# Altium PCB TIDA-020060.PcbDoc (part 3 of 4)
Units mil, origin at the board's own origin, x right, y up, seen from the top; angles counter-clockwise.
Board outline 2114.94 x 3612.21 mil, 4 copper layers (Top Layer, Signal Layer 1, Signal Layer 2, Bottom Layer), stack 61.811 mil thick; 272 components, 167 nets, 840 pads, 352 vias.
Unrouted connection lines stored in the file: 261.
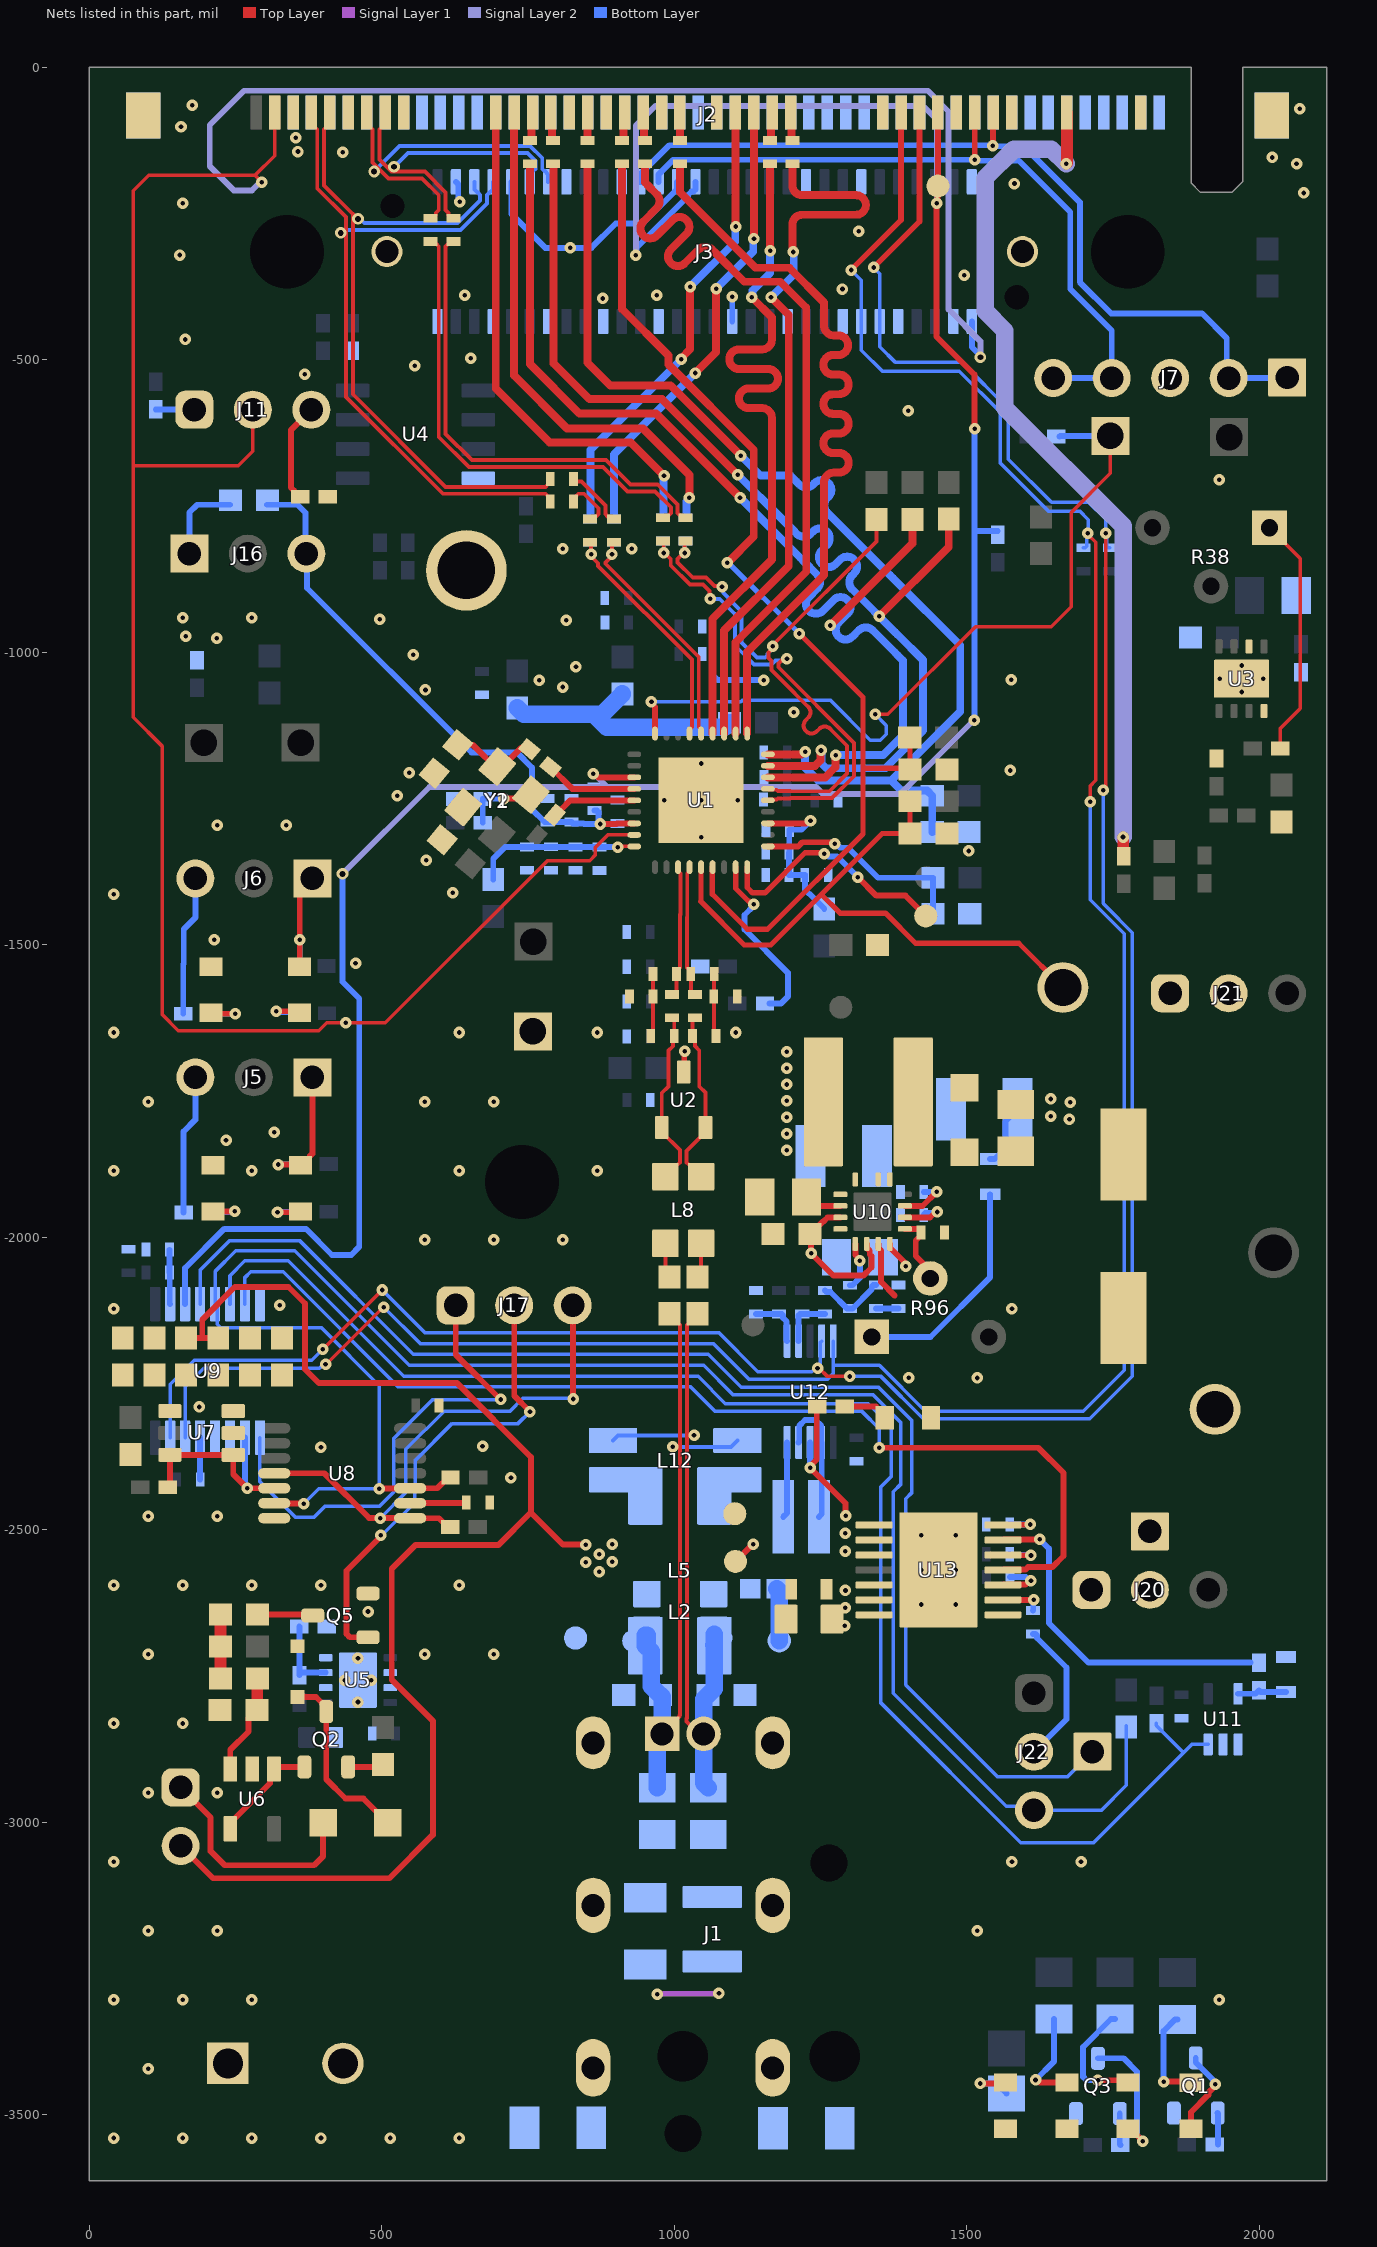
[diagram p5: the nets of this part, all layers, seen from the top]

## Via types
v1: diameter 19.68, hole 7.87, Top Layer to Bottom Layer, tented both sides, 333 vias
v2: diameter 19.68, hole 7.87, Top Layer to Bottom Layer, 10 vias
v3: diameter 20, hole 10, Top Layer to Bottom Layer, 7 vias
v4: diameter 50, hole 28, Top Layer to Bottom Layer, 2 vias

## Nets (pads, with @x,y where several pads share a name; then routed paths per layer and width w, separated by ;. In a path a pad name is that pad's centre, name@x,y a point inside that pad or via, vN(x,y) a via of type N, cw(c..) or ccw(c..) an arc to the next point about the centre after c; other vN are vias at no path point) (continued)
AE_MDIO: J8.1 R19.1 U1.36 | length 1352.1
  Top Layer w6: v1(1343.12,-1106.01) 1364.59,-1106.01 1514.69,-955.91 1644.26,-955.91 1678.02,-922.15 1678.02,-760.89 1745.25,-693.65 J8.1@1745.25,-629.91
  Top Layer w10: v1(960.75,-1084.6) 960.75,-1087.19 966.84,-1093.28 U1.36@966.84,-1138.68
  Bottom Layer w6: v1(960.75,-1084.6) 960.79,-1084.56 1113.73,-1084.56 1116.92,-1081.37 1266.21,-1081.37 1335.02,-1150.19 1351.61,-1150.19 1362.06,-1139.74 1362.06,-1124.95 v1(1343.12,-1106.01)
  Bottom Layer w10: R19.1@1658.4,-631.06 1659.55,-629.91 J8.1@1745.25,-629.91
AE_RESET_N: J2.26 J3.45 R20.1 TP13.1 U1.3 U9.3 | length 4542
  Top Layer w10: v1(861.53,-1207.49) 864.15,-1207.49 870.29,-1213.63 U1.3@931.41,-1213.63 ; v1@1447.74,-231.69 1449.56,-229.87 1449.56,-203.71 TP13.1@1450.43,-202.84 ; v1(1448.69,-232.32) 1447.74,-233.27 1447.74,-459.82 1513.1,-525.18 v1(1513.1,-617.84) ; TP13.1@1450.43,-200.02 J2.26@1450.43,-77
  Signal Layer 2 w10: v3(432.73,-1378.58) 581.23,-1230.08 885.38,-1230.08 ; v1(861.53,-1207.49) 862.8,-1207.49 885.38,-1230.08 ; v1(934.05,-321.37) 934.05,-99.29 967.38,-65.95 1425.39,-65.95 1448.69,-89.25 v1(1448.69,-232.32) ; v1(1512.24,-1115.65) 1385.6,-1242.29 1254.46,-1242.29 1242.25,-1230.08 885.38,-1230.08
  Bottom Layer w10: U9.3@163.56,-2113.84 163.56,-2052.49 230.7,-1985.35 370.12,-1985.35 414.72,-2029.94 447.48,-2029.94 461.36,-2016.06 461.36,-1591.68 432.73,-1563.06 v3(432.73,-1378.58) ; v1(934.05,-321.37) 935.74,-319.68 935.74,-307.93 1023.35,-220.32 1023.35,-218.18 1029.2,-212.32 1032.13,-212.32 1035.98,-208.46 J3.45@1035.98,-195.67 ; v1(1512.24,-1115.65) 1512.67,-1115.22 1512.67,-792.2 ; v1(1513.1,-617.84) 1512.67,-618.27 1512.67,-792.2 ; R20.1@1552.78,-792.63 1513.1,-792.63 1512.67,-792.2
AE_RX_CLK: R14.2 R54.2 R59.2 U1.27 | length 1893.6
  Top Layer w13.5: U1.27@1159.75,-1174.26 1217.32,-1174.26 1221.7,-1169.88 v1(1223.37,-1169.88)
  Top Layer w13.51: R54.2@851.26,-164.75 851.26,-504.76 890.34,-543.84 993.53,-543.84 v1(1113.25,-663.56)
  Bottom Layer w13.5: v1(1113.25,-663.56) 1147.6,-697.91 1198.63,-697.91 1208.77,-708.05 1213.54,-712.83 ccw(c1225.39,-700.98) 1237.23,-712.83 1239.64,-710.42 cw(c1251.48,-722.27) 1263.33,-710.42 cw(c1251.48,-722.27) 1263.33,-734.11 1260.92,-736.52 ccw(c1272.77,-748.36) 1260.92,-760.21 1368.6,-867.89 1373.38,-872.66 1488.62,-987.91 1488.62,-1101.13 1370.68,-1219.07 1248.07,-1219.07 1245.44,-1218.63 1223.36,-1196.55 v1(1223.37,-1169.88)
  Bottom Layer w13.51: 1370.68,-1219.07 1387.67,-1236.05 1431.69,-1236.05 R14.2@1440.75,-1245.11 R59.2@1440.75,-1306.71
AE_RX_CTRL: R31.1 R53.2 R67.2 U1.15 | length 1886.2
  Top Layer w9: U1.15@1065.26,-1367.03 1064.86,-1367.44 1064.86,-1413.46 1124.64,-1473.25 1159.14,-1473.25 1322.16,-1310.23 1322.16,-1198.02 ; v1(1213.28,-967.75) 1322.16,-1076.63 1322.16,-1198.02 ; R31.1@1402.3,-1145.38 1402.52,-1145.6 R67.2@1402.52,-1199.61 ; R67.2@1402.74,-1199.83 R67.2@1402.52,-1199.61 ; 1322.16,-1198.02 1400.93,-1198.02 R67.2@1402.52,-1199.61
  Top Layer w13.51: R53.2@910.69,-164.75 910.69,-413.48 989.87,-492.66 989.87,-507.77 1135.61,-653.51 1135.61,-802.02 v1(1090.59,-847.04)
  Bottom Layer w9: v1(1090.59,-847.04) 1092.56,-847.04 v1(1213.28,-967.75)
AE_RX_D0: R3.2 R55.2 U1.26 | length 1966.1
  Top Layer w13.5: U1.26@1159.75,-1193.94 1240.23,-1193.94 1249.47,-1184.71 1249.47,-1168.76 v1(1250.66,-1167.58)
  Top Layer w13.51: R55.2@792.85,-164.75 792.85,-164.9 793.45,-165.5 793.45,-505.87 854.74,-567.16 978.66,-567.16 1107.77,-696.27 v1(1108.05,-696.27) ; v1(1350.17,-938.39) 1468.87,-819.7 1468.87,-772.28 R3.2@1468.93,-772.21
  Bottom Layer w13.5: 1182.87,-771.09 1204.29,-792.51 1209.06,-797.28 ccw(c1220.91,-785.44) 1232.76,-797.28 1236.84,-793.2 cw(c1248.69,-805.04) 1260.53,-793.2 cw(c1248.69,-805.04) 1260.53,-816.89 1252.05,-825.37 ccw(c1263.9,-837.21) 1252.05,-849.06 ccw(c1263.9,-837.21) 1275.74,-849.06 1283.53,-841.27 cw(c1295.37,-853.12) 1307.22,-841.27 cw(c1295.37,-853.12) 1307.22,-864.96 1303.83,-868.36 ccw(c1315.67,-880.2) 1303.83,-892.05 1376.78,-965 1381.55,-969.77 1424.89,-1013.11 ; v1(1250.66,-1167.58) 1251.84,-1168.76 1251.84,-1190.11 1259.75,-1198.02 1360.54,-1198.02 1424.89,-1133.67
  Bottom Layer w13.51: v1(1108.05,-696.27) 1182.87,-771.09 ; 1424.89,-1133.67 1424.89,-1013.11
AE_RX_D1: R4.2 R56.2 U1.25 | length 2006.2
  Top Layer w13.5: U1.25@1159.75,-1213.63 1257.76,-1213.63 1275.03,-1196.36 1275.03,-1176.68 v1(1276.05,-1175.65)
  Top Layer w13.51: R56.2@753.36,-164.75 753.36,-165.23 753.1,-165.5 753.1,-507.09 837.54,-591.53 968.36,-591.53 v1(1112.2,-735.37) ; v1(1266.49,-953.97) 1406.92,-813.55 1406.92,-772.54 R4.2@1406.98,-772.48
  Bottom Layer w13.5: v1(1112.2,-735.37) 1215.72,-838.9 1220.5,-843.67 1244.19,-867.37 cw(c1232.34,-879.21) 1244.19,-891.06 1229.93,-905.32 ccw(c1241.77,-917.17) 1229.93,-929.01 ccw(c1241.77,-917.17) 1253.62,-929.01 1272.27,-910.35 cw(c1284.12,-922.2) 1295.97,-910.35 cw(c1284.12,-922.2) 1295.97,-934.04 1280.6,-949.41 ccw(c1292.45,-961.25) 1280.6,-973.1 ccw(c1292.45,-961.25) 1304.29,-973.1 1315.26,-962.13 cw(c1327.11,-973.97) 1338.95,-962.13 1376.75,-999.92 1381.52,-1004.7 1390.92,-1014.09 1390.92,-1141.47 1356.9,-1175.49 1276.21,-1175.49 v1(1276.05,-1175.65)
  Bottom Layer w13.51: v1(1266.49,-953.97) 1267.74,-952.73 1277.28,-952.73 1280.6,-949.41
AE_RX_N: R39.2 R58.2 U1.23 | length 808
  Top Layer w6.73: R39.2@980.32,-809.77 981.8,-811.25 v1(981.8,-829.98) 983.03,-829.98 993.73,-840.68 993.73,-851.12 1026.45,-883.84 1048.94,-883.84 1059.88,-894.78 1059.88,-906.48 v1(1061.39,-908) ; U1.23@1159.75,-1252.86 1161.31,-1251.3 1174.82,-1251.3 1176.65,-1249.48 1197.82,-1249.48 1198.27,-1249.02 1269.73,-1249.02 1307.04,-1211.71 1307.04,-1154.64 1177.72,-1025.32 1177.72,-1018.95 1183.2,-1013.48 1189.91,-1013.48 v1(1192.39,-1011)
  Bottom Layer w6.73: R58.2@980.32,-809.77 981.8,-811.25 v1(981.8,-829.98) ; v1(1061.39,-908) 1062.34,-908.95 1077.49,-908.95 1103.19,-934.65 1103.19,-987.78 1136.08,-1020.67 1165.75,-1020.67 1172.94,-1013.48 1189.91,-1013.48 v1(1192.39,-1011)
AE_RX_P: R5.2 R40.2 R57.2 U1.24 | length 1087.2
  Top Layer w6.73: R40.2@1019.02,-809.77 1017.38,-811.4 v1(1017.38,-829.98) 1016.16,-829.98 1005.46,-840.68 1005.46,-846.26 1031.31,-872.11 1053.8,-872.11 1068.17,-886.48 1079.88,-886.48 v1(1081.39,-888) ; U1.24@1159.75,-1233.17 1161.31,-1234.73 1174.54,-1234.73 1176.65,-1236.84 1197.82,-1236.84 1198.27,-1237.29 1264.87,-1237.29 1295.31,-1206.85 1295.31,-1159.5 1268.82,-1133.01 1266.44,-1130.63 ccw(c1256.98,-1140.08) 1247.53,-1130.63 1243.59,-1134.57 cw(c1234.14,-1125.12) 1224.69,-1134.57 cw(c1234.14,-1125.12) 1224.69,-1115.67 1228.63,-1111.72 ccw(c1219.18,-1102.27) 1228.63,-1092.82 1183.62,-1047.81 1165.99,-1030.18 1165.99,-1014.54 1160.98,-1009.53 1160.98,-1000.48 1168.38,-993.09 v1(1168.38,-989.58) 1168.38,-986.91 1345.18,-810.1 1345.18,-772.81 R5.2@1345.25,-772.75
  Bottom Layer w6.73: v1(1017.38,-829.98) 1017.38,-811.4 R57.2@1019.02,-809.77 ; 1083.87,-898.73 1114.92,-929.79 1114.92,-982.92 1140.94,-1008.94 1154.77,-1008.94 1158.72,-1005 1158.72,-1002.74 1168.38,-993.09 v1(1168.38,-989.58)
AE_STRP_1: R29.2 R35.2 TP4.1 U1.14 | length 1060.1
  Top Layer w9: U1.14@1045.58,-1367.03 1045.58,-1425.37 1045.17,-1425.78 1119.44,-1500.05 1164.64,-1500.05 1251.04,-1413.65 ; R29.2@1402.65,-1254.42 R35.2@1402.65,-1309.42 1355.28,-1309.42 1251.04,-1413.65 ; TP4.1@1664.13,-1572.77 1588.6,-1497.25 1412.41,-1497.25 1360.9,-1445.73 1283.13,-1445.73 1251.04,-1413.65
AE_STRP_DFT: TP5.1 U1.18 | length 416.9
  Top Layer w9: U1.18@1124.32,-1367.03 1124.32,-1401.57 1126.3,-1403.55 1133.77,-1411.02 1154.66,-1411.02 1223.19,-1342.49 1254.37,-1342.49 v1(1256.21,-1344.34)
  Top Layer w10: v1(1313.68,-1384.3) 1345.14,-1415.77 1394.94,-1415.77 TP5.1@1429.63,-1450.46
  Bottom Layer w10: v1(1256.21,-1344.34) 1258.83,-1344.34 1263.28,-1348.79 1278.17,-1348.79 v1(1313.68,-1384.3)
AE_TX_CLK: R51.2 U1.28 | length 1392.4
  Top Layer w13.51: R51.2@1009.46,-164.75 1009.46,-213.36 1138.63,-342.53 1196.4,-342.53 1255.62,-401.76 1255.62,-412.6 1255.62,-441.37 ccw(c1272.38,-441.37) 1272.38,-458.12 1280.21,-458.12 cw(c1280.21,-474.87) 1296.97,-474.87 cw(c1280.21,-474.87) 1280.21,-491.63 1271.32,-491.63 ccw(c1271.32,-508.38) 1254.56,-508.38 ccw(c1271.32,-508.38) 1271.32,-525.14 1281.25,-525.14 cw(c1281.25,-541.89) 1298,-541.89 cw(c1281.25,-541.89) 1281.25,-558.65 1271.32,-558.65 ccw(c1271.32,-575.4) 1254.56,-575.4 ccw(c1271.32,-575.4) 1271.32,-592.16 1281.25,-592.16 cw(c1281.25,-608.91) 1298,-608.91 cw(c1281.25,-608.91) 1281.25,-625.67 1271.32,-625.67 ccw(c1271.32,-642.42) 1254.56,-642.42 ccw(c1271.32,-642.42) 1271.32,-659.18 1281.25,-659.18 cw(c1281.25,-675.93) 1298,-675.93 cw(c1281.25,-675.93) 1281.25,-692.69 1272.38,-692.69 ccw(c1272.38,-709.44) 1255.62,-709.44 1255.62,-749.71 1255.62,-867.9 1124.32,-999.21 U1.28@1124.32,-1138.68
AE_TX_CTRL: R52.2 U1.29 | length 1391.4
  Top Layer w13.51: R52.2@950.04,-164.75 950.04,-197.01 954.82,-201.78 969.83,-216.8 cw(c957.98,-228.64) 969.83,-240.49 946.65,-263.67 ccw(c958.5,-275.51) 946.65,-287.36 ccw(c958.5,-275.51) 970.35,-287.36 997.01,-260.7 cw(c1008.85,-272.55) 1020.7,-260.7 cw(c1008.85,-272.55) 1020.7,-284.4 994.04,-311.06 ccw(c1005.89,-322.9) 994.04,-334.75 ccw(c1005.89,-322.9) 1017.74,-334.75 1040.91,-311.57 cw(c1052.76,-323.42) 1064.61,-311.57 1069.38,-316.35 1119.45,-366.42 1180.99,-366.42 1225.3,-410.73 1225.3,-861.89 1104.63,-982.56 U1.29@1104.63,-1138.68
AE_TX_D2: R48.2 U1.31 | length 1264.8
  Top Layer w13.51: U1.31@1065.26,-1138.68 1065.26,-942.61 1166.64,-841.23 1166.64,-606 1166.64,-599.24 ccw(c1149.89,-599.24) 1149.89,-582.49 1126.98,-582.49 cw(c1126.98,-565.73) 1110.23,-565.73 cw(c1126.98,-565.73) 1126.98,-548.98 1160.21,-548.98 ccw(c1160.21,-532.23) 1176.97,-532.23 ccw(c1160.21,-532.23) 1160.21,-515.47 1110.58,-515.47 cw(c1110.58,-498.72) 1093.82,-498.72 cw(c1110.58,-498.72) 1110.58,-481.96 1149.89,-481.96 ccw(c1149.89,-465.21) 1166.64,-465.21 1166.64,-434.25 1166.64,-427.32 v1(1132.4,-393.08) ; R48.2@1163.04,-164.75 1163.31,-165.02 1163.31,-312.81 v1(1163.58,-313.08)
  Bottom Layer w13.51: v1(1132.4,-393.08) 1133.58,-391.89 1133.58,-381.65 1163.58,-351.65 v1(1163.58,-313.08)
AE_TX_D3: R47.2 U1.30 | length 1271.7
  Top Layer w13.51: U1.30@1084.95,-1138.68 1084.95,-962.67 1195.48,-852.15 1195.48,-423.41 v1(1165.14,-393.08) ; R47.2@1201.66,-164.75 1201.66,-165.54 1201.66,-201.67 ccw(c1218.41,-201.67) 1218.41,-218.42 1310.45,-218.42 cw(c1310.45,-235.18) 1327.21,-235.18 cw(c1310.45,-235.18) 1310.45,-251.93 1218.41,-251.93 ccw(c1218.41,-268.69) 1201.66,-268.69 1201.66,-308.95 1201.66,-314.31 v1(1202.83,-315.48)
  Bottom Layer w13.51: v1(1165.14,-393.08) 1204.01,-354.21 1204.01,-316.66 v1(1202.83,-315.48)
AE_TX_N: R46.2 R50.2 U1.33 | length 422
  Top Layer w6.73: R46.2@855.56,-811.74 857.65,-813.83 v1(857.65,-832.13) 857.65,-835.63 869.65,-847.63 869.65,-852.26 1029.87,-1012.48 1029.87,-1127.82 1025.89,-1131.8 U1.33@1025.89,-1138.68
  Bottom Layer w6.73: R50.2@855.56,-811.74 857.65,-813.83 v1(857.65,-832.13)
AE_TX_P: R45.2 R49.2 U1.32 | length 422
  Top Layer w6.73: R45.2@896.44,-811.74 893.23,-814.95 v1(893.23,-832.13) 893.23,-835.63 882.46,-846.4 882.46,-848.48 1041.6,-1007.62 1041.6,-1127.82 1045.58,-1131.8 U1.32@1045.58,-1138.68
  Bottom Layer w6.73: v1(893.23,-832.13) 893.23,-814.95 R49.2@896.44,-811.74
AE_VSLEEP: C2.1 C3.1 C37.1 C43.2 J16.3 R2.1 U1.7 | length 1029.5
  Top Layer w10: v1(873.27,-1293.31) 900.67,-1293.31 901.75,-1292.23 U1.7@931.41,-1292.23
  Bottom Layer w10: R2.1@303.38,-747.51 355.69,-747.51 369.44,-761.26 369.44,-829.71 371.91,-832.18 371.91,-889.72 653.05,-1170.86 730.4,-1170.86 756.35,-1196.81 756.35,-1268 778.23,-1289.88 C2.1@782.73,-1289.88 C3.1@824.02,-1289.88 826.52,-1292.38 844.81,-1292.38 845.74,-1293.31 v1(873.27,-1293.31) ; C37.1@863.34,-1270.2 867.84,-1270.2 870.34,-1272.7 870.34,-1287.76 873.27,-1290.69 v1(873.27,-1293.31) ; C43.2@902.46,-1292.31 901.96,-1292.81 873.77,-1292.81 v1(873.27,-1293.31)
AE_WAKE: J2.98 J3.30 J11.2 U1.8 | length 5029.2
  Top Layer w6: J11.2@279.34,-585.09 279.34,-655.89 254.29,-680.94 76.45,-680.94 75.02,-679.52 ; v1(294.51,-196.06) 283.02,-184.57 ; J2.98@316.57,-77 316.77,-77.2 316.77,-150.82 283.02,-184.57 ; U1.8@931.41,-1312.06 886.33,-1312.06 865.05,-1333.33 865.05,-1345.98 855.09,-1355.93 783.01,-1355.93 505.98,-1632.96 v1(438.08,-1632.96) 405.79,-1632.96 392.35,-1646.4 151.88,-1646.4 124.14,-1618.66 124.14,-1160.06 75.02,-1110.95 75.02,-679.52 ; 75.02,-679.52 75.02,-210.94 101.4,-184.57 283.02,-184.57
  Signal Layer 2 w10: v1(294.51,-196.06) 291.89,-196.06 277.82,-210.13 246.82,-210.13 205.84,-169.15 205.84,-98.47 264.31,-40 1433.37,-40 1468.69,-75.32 1468.69,-288.08 1468.56,-288.21 1468.56,-413.64 1522.97,-468.05 v3(1522.97,-495.34)
  Bottom Layer w10: J3.30@1508.43,-434.25 1508.43,-478.09 1522.97,-492.63 v3(1522.97,-495.34)
AE_XI: R69.1 U1.5 | length 143
  Top Layer w10: R69.1@794.84,-1268.33 806.35,-1268.33 821.82,-1252.86 U1.5@931.41,-1252.86
AE_XO: R30.1 U1.4 | length 158.5
  Top Layer w10: R30.1@788.27,-1196.02 825.43,-1233.17 U1.4@931.41,-1233.17
BAW_NC: C28.1 R30.2 Y1.1 Y2.1 | length 154.2
  Top Layer w10: C28.1@629.9,-1158.23 630.18,-1157.96 655.3,-1157.96 Y2.1@699.22,-1201.88 ; Y2.1@701.63,-1199.47 735.45,-1165.65 735.51,-1165.65 738.04,-1163.12 749.55,-1163.12 R30.2@752.08,-1165.65
BOOST_PG: U10.4
comp_out: R86.1 U7.1 U7.6 U8.5 U9.10 | length 366.5
  Top Layer w10: R86.1@134.18,-2427.1 137.62,-2423.65 U7.6@137.62,-2371.68 U7.1@245.89,-2371.68 245.89,-2404.99 v1(269.64,-2428.74) U8.5@316.01,-2428.74
  Bottom Layer w10: U9.10@265.93,-2342.19 265.93,-2422.32 269.64,-2426.03 v1(269.64,-2428.74)
DUT_VDD1P0: J2.12 R16.1 | length 1515.3
  Top Layer w19.68: v1(1766.86,-1315.6) 1767.4,-1316.14 1767.4,-1347.92 R16.1@1767.94,-1348.46
  Top Layer w20: v1(1669.68,-164.74) 1670.9,-163.51 J2.12@1670.9,-77
  Signal Layer 2 w10: v1(1766.86,-1315.6) v1@1766.86,-1315.12
  Signal Layer 2 w30: v1(1669.68,-164.74) 1644.5,-139.56 1580.45,-139.56 1531.13,-188.88 1531.13,-416.38 1565.03,-450.28 1565.03,-582.06 1766.86,-783.9 v1@1766.86,-1315.12
EN: J22.2 R112.1 | length 250.5
  Bottom Layer w10: R112.1@1612.91,-2677.88 1617.41,-2677.88 1619.91,-2680.38 1619.91,-2684.88 1670.06,-2735.04 1670.06,-2823.53 J22.2@1614.54,-2879.06
EN_detection: J17.2 Q5.1 | length 809
  Top Layer w10: Q5.1@476.26,-2683.53 445.22,-2683.53 439.36,-2677.68 439.36,-2569.76 498.34,-2510.78 v1(498.34,-2509.39) ; J17.2@726.13,-2116.18 726.13,-2270.7 v1(753.11,-2297.68)
  Bottom Layer w6: v1(498.34,-2509.39) 499.97,-2509.39 555.92,-2453.43 555.92,-2436.37 557.32,-2434.97 557.32,-2380.7 619.9,-2318.12 732.67,-2318.12 v1(753.11,-2297.68)
EN_detection_SoC: J17.1 U9.9 | length 841.5
  Top Layer w10: J17.1@626.13,-2116.18 626.13,-2200.33 702.82,-2277.02 v1(702.93,-2277.02)
  Bottom Layer w6: U9.9@291.52,-2342.19 291.52,-2417.88 351.58,-2477.95 384.59,-2477.95 402.62,-2459.92 495.76,-2459.92 520.65,-2435.03 520.65,-2343.51 587.03,-2277.13 702.82,-2277.13 v1(702.93,-2277.02)
EN_P17: R62.2 U1.17 | length 309.5
  Top Layer w9: U1.17@1104.63,-1367.03 1104.63,-1403.1 1127.06,-1425.52 1128.02,-1425.52 1132.95,-1430.45 v1(1135.57,-1430.45)
  Bottom Layer w10: v1(1135.57,-1430.45) 1135.57,-1433.07 1119.79,-1448.85 1119.79,-1473.35 1193.92,-1547.48 1193.92,-1588.43 1182.43,-1599.92 R62.2@1162.74,-1599.92
ext_pwr_supply: J14.2 J20.1 J21.1
FB: R96.2 R101.2 U10.9 | length 124.7
  Top Layer w10: U10.9@1393.93,-1985.5 1394.2,-1985.78 1419.12,-1985.78 1421.62,-1988.28 1421.62,-1996.11 1412.48,-2005.24 1412.48,-2031.82 1437.4,-2056.74 R96.2@1437.4,-2070.01
GND: C2.2 C3.2 C4.2 C5.1 C6.2 C7.1 C8.2 C11.2 C12.2 C13.2 C14.1 C15.2 C16.2 C17.2 C18.1 C19.1 C22.2 C23.2 C24.2 C25.2 C26.1 C27.2 C28.2 C29.2 C30.1 C31.1 C32.1 C35.2 C37.2 C38.2 C39.2 C40.1 C41.2 C42.2 C43.1 C44.2 C45.2 C46.1 C47.2 C48.1 C49.2 C50.2 C51.2 C52.2 C53.2 C54.1 C55.1 C56.2 C57.2 C58.2 C59.2 C60.2 C61.2 C62.2 C63.2 C64.1 C65.2 C67.2 C68.2 C69.2 C70.2 D1.1 D2.2 D3.2 D4.2 D7.1 D8.1 D13.1 D15.1 J2.4 J2.9 J2.11 J2.13 J2.15 J2.17 J2.18 J2.19 J2.21 J2.23 J2.24 J2.25 J2.27 J2.29 J2.31 J2.32 J2.33 J2.35 J2.37 J2.39 J2.41 J2.43 J2.45 J2.47 J2.49 J2.50 J2.51 J2.53 J2.55 J2.56 J2.57 J2.59 J2.61 J2.62 J2.63 J2.65 J2.66 J2.67 J2.69 J2.71 J2.73 J2.75 J2.77 J2.79 J2.81 J2.83 J2.84 J2.85 J2.87 J2.89 J2.90 J2.91 J2.93 J2.95 J2.96 J2.MP1 J2.MP2 J2.MP3 J2.MP4 J3.1 J3.4 J3.7 J3.10 J3.13 J3.17 J3.20 J3.23 J3.26 J3.29 J3.32 J3.35 J3.38 J3.41 J3.44 J3.51 J3.54 J3.60 J3.MH1 J3.MH2 J7.3 J13.1 J14.1 Q1.2 Q3.2 Q5.2 R13.1 R18.2 R24.1 R35.1 R37.1 R41.2 R59.1 R60.2 R67.1 R80.1 R87.1 R88.1 R89.1 R92.1 R99.1 R101.1 R102.1 R106.2 R107.2 R108.1 R111.1 R115.1 R116.1 TP8.1 TP24.1 U1.37 U2.3 U3.4 U3.9 U4.4 U5.2 U5.4 U5.6 U5.7 U5.9 U6.2 U7.2 U8.7 U9.8 U10.1 U10.7 U10.16 U11.1 U11.2 U12.7 U12.9 U13.1 U13.15 Y1.2 Y2.2 | length 1179.2
  Top Layer w10: U2.3@1015.91,-1717.4 1016.86,-1716.44 1016.86,-1682.58 v1(1017.92,-1681.52) ; U10.7@1348.65,-2011.09 1348.65,-2017.63 1353.34,-2022.31 1353.34,-2076.11 1376.68,-2099.45
  Signal Layer 1 w10: v1(970.68,-3293.89) 971.66,-3292.9 1075.18,-3292.9 v1(1076.16,-3291.92)
  Bottom Layer w10: J3.32@626.54,-195.67 630.39,-199.53 630.39,-224.3 633.31,-227.22 v1(633.31,-229.84) ; J3.35@721.02,-195.67 721.02,-250.29 779.2,-308.47 v1(822.19,-308.47) 858.03,-308.47 899.72,-266.78 946.18,-266.78 1004.49,-208.46 J3.44@1004.49,-195.67 ; 1066.99,-1040 1074.38,-1047.4 v1(1152.44,-1047.4) ; v1(1098.86,-392.29) 1098.86,-434.37 J3.17@1098.98,-434.25 ; U12.9@1212.4,-2350.47 1213.3,-2349.56 1213.3,-2321.8 1223.18,-2311.92 1240.99,-2311.92 1250.86,-2321.8 1250.86,-2349.56 U12.7@1251.77,-2350.47 1251.77,-2472.88 R108.1@1247.07,-2477.58 ; R106.2@1257.4,-2090.82 1259.9,-2093.32 1266.95,-2093.32 1295.33,-2121.7 R102.1@1299.83,-2121.7 1304.33,-2121.7 1337.38,-2088.65 1337.38,-2083.94 1339.88,-2081.44 C62.2@1344.38,-2081.44
  other v1: 41.54,-3539.46 159.65,-3539.46 277.76,-3539.46 395.87,-3539.46 513.98,-3539.46 632.09,-3539.46 100.59,-3421.35 41.54,-3303.24 159.65,-3303.24 277.76,-3303.24 1931.3,-3303.24 100.59,-3185.13 218.7,-3185.13 1517.92,-3185.13 41.54,-3067.02 1576.97,-3067.02 1695.08,-3067.02 100.59,-2948.91 218.7,-2948.91 41.54,-2830.8 159.65,-2830.8 459.09,-2794.15 436.45,-2756.75 481.72,-2756.75 459.09,-2719.35 100.59,-2712.69 573.03,-2712.69 691.14,-2712.69 476.31,-2639.49 1421.82,-2627.45 1480.87,-2627.45 41.54,-2594.58 159.65,-2594.58 277.76,-2594.58 395.87,-2594.58 632.09,-2594.58 1421.82,-2568.4 1480.87,-2568.4 1421.82,-2509.34 1480.87,-2509.34 100.59,-2476.47 218.7,-2476.47 720.58,-2410.98 395.87,-2358.35 672,-2356.89 187.89,-2289.77 1517.92,-2240.24 1400.25,-2239.8 41.54,-2122.13 1576.97,-2122.13 325.42,-2115.63 573.03,-2004.02 691.14,-2004.02 809.25,-2004.02 41.54,-1885.91 277.76,-1885.91 632.09,-1885.91 868.31,-1885.91 233.53,-1834.16 316.16,-1820.39 100.59,-1767.8 573.03,-1767.8 691.14,-1767.8 41.54,-1649.69 632.09,-1649.69 868.31,-1649.69 1104.53,-1649.69 454.92,-1531.58 213.17,-1491.33 41.54,-1413.47 621.17,-1410.84 575.67,-1355.2 1502.8,-1339.4 218.7,-1295.36 336.81,-1295.36 526.01,-1245.23 547.07,-1205.45 1574.33,-1201.77 1203.72,-1101.99 1969.45,-1067.58 574.47,-1064.22 809.25,-1059.14 768.7,-1047.62 1576.06,-1047.06 1932.05,-1044.94 2006.85,-1044.94 831.71,-1024.71 1969.45,-1022.31 553.74,-1004.04 217.99,-976.11 164.83,-972.55 814.89,-944.96 496.47,-943.08 159.65,-941.03 277.76,-941.03 809.25,-822.92 927.36,-822.92 1931.3,-704.81 1399.8,-586.7 368.03,-524.24 555.82,-510.3 651.77,-496.96 163.69,-465.08 877.35,-394.98 641.45,-389.79 969.71,-389.81 1287.28,-378.82 1495.43,-355.21 154.58,-320.73 1315.01,-280.23 159.65,-232.37 2075.5,-214.67 1581.29,-198.48 2063.43,-164.48 2022.13,-153.99 432.77,-144.78 356.49,-143.78 352.98,-120.53 156.58,-101.18 2068.83,-70.45 175.61,-64.56
  other v2: 1045.58,-1315.85 982.59,-1252.86 1045.58,-1252.86 1108.57,-1252.86 1045.58,-1189.87
GND_WIRE: C19.2 J1.S1 J1.S2 J1.S3 J1.S4 J1.S5 J1.S6 R18.1
GPIO6: U9.11
GPIO7: U9.12
GPIO_3: R6.2 R24.2 U1.19 | length 372.4
  Top Layer w10: U1.19@1159.75,-1331.6 1211.3,-1331.6 1211.44,-1331.74 1218.68,-1324.49 1268.75,-1324.49 1271.59,-1327.34 v1(1274.21,-1327.34)
  Bottom Layer w10: v1(1274.21,-1327.34) 1276.83,-1327.34 1283.28,-1333.79 1296.67,-1333.79 1348.02,-1385.13 R6.2@1442.26,-1385.13 1441.85,-1385.55 R24.2@1441.85,-1446.62
GPIO_4: J2.7
GPIO_5: J2.5
GPIO_6: J2.3
GPIO_7: J2.1
High_side_sw_VIN: C67.1 C68.1 J20.2 U13.12 U13.13 U13.14
  other v1: 1291.47,-2664.04 1292.05,-2633.33 1292.36,-2603.5
HSS_EN: J23.1 U9.4 | length 2281.2
  Bottom Layer w6: U9.4@189.15,-2113.84 189.15,-2056.26 240.09,-2005.32 359.16,-2005.32 553.28,-2199.45 1057.73,-2199.45 1114.25,-2255.97 1348.84,-2255.97 1406.03,-2313.15 1406.03,-2436.01 1395.16,-2446.88 1395.16,-2765.01 1551.69,-2921.54 1672.06,-2921.54 J23.1@1714.54,-2879.06
HSS_FAULT: U9.7 U13.4 | length 1865.2
  Top Layer w10: v1(1350.28,-2359.49) 1622.08,-2359.49 1665.05,-2402.46 1665.05,-2544.51 1645.95,-2563.61 1604.3,-2563.61 1600.41,-2567.49 1562.49,-2567.49 U13.4@1561.58,-2568.4
  Bottom Layer w6: U9.7@265.93,-2113.84 265.93,-2068.49 275.53,-2058.89 331.53,-2058.89 528.22,-2255.58 1027.75,-2255.58 1069.62,-2297.45 1320.71,-2297.45 1350.28,-2327.02 v1(1350.28,-2359.49)
HSS_SNS: R70.1 U9.6 U11.3 | length 2583.5
  Bottom Layer w6: U9.6@240.34,-2113.84 240.34,-2065.24 265.61,-2039.97 339.97,-2039.97 537.49,-2237.49 1040.56,-2237.49 1087.12,-2284.05 1331.08,-2284.05 1370.28,-2323.24 1370.28,-2409.23 1353.12,-2426.39 1353.12,-2795.91 1591.78,-3034.57 1716.45,-3034.57 1870.55,-2880.47 ; R70.1@1823.87,-2830.32 1823.87,-2834.26 1870.08,-2880.47 1870.55,-2880.47 ; U11.3@1912.34,-2866.68 1884.35,-2866.68 1870.55,-2880.47
MDC: J2.20 J3.42 J7.1 J7.2 | length 1480
  Top Layer w10: v1(1543.97,-133.83) 1544.45,-133.36 1544.45,-77.47 J2.20@1544.92,-77
  Bottom Layer w10: J3.42@941.5,-195.67 941.5,-182.87 991.39,-132.98 1543.12,-132.98 1544.82,-134.69 1597.1,-134.69 1693.01,-230.6 1693.01,-367.05 1746.64,-420.68 1902.12,-420.68 1944.19,-462.75 1944.19,-527.73 J7.2@1947.5,-531.05 2046.5,-531.05 J7.1@2047.5,-530.05
MDIO: J2.22 J3.43 J7.4 J7.5 | length 1257.9
  Top Layer w10: v1(1513.42,-157.83) J2.22@1513.42,-77
  Bottom Layer w10: J3.43@972.99,-195.67 972.99,-182.87 998.04,-157.83 v1(1513.42,-157.83) 1515.28,-159.68 1589.11,-159.68 1676.57,-247.15 1676.57,-378.92 1747.5,-449.85 J7.4@1747.5,-531.05 J7.5@1647.5,-531.05
NetC7_2: C7.2 C9.1 R7.2 | length 107.6
  Top Layer w6.73: R7.2@959.71,-1655.41 959.71,-1650.91 963.44,-1647.18 C7.2@963.44,-1588.23 ; C7.2@963.44,-1588.23 C9.1@963.48,-1549.41
NetC21_2: C21.2 C27.1 R10.1 | length 107.8
  Top Layer w6.73: C21.2@1068.06,-1549.41 1067.7,-1549.77 1067.7,-1588.01 C27.1@1067.35,-1588.37 1067.35,-1647.35 1070.9,-1650.91 R10.1@1070.9,-1655.41
NetC50_1: C50.1 R79.2 U6.3 | length 173.8
  Top Layer w10: U6.3@240.87,-2908.58 240.87,-2875.74 271.81,-2844.81 271.81,-2821.66 285.51,-2807.96 C50.1@286.49,-2807.96
  Top Layer w20: C50.1@287,-2807.45 R79.2@287,-2753.78
NetC52_1: C52.1 R82.1 R88.2 U7.4
NetC53_1: C53.1 R83.1 R89.2 U7.3
NetC59_1: C59.1 U10.2 | length 64
  Top Layer w10: C59.1@1225.97,-1930.98 1241.12,-1946.13 U10.2@1283.69,-1946.13
NetC60_1: C60.1 U10.10 | length 84.7
  Top Layer w10: U10.10@1393.93,-1965.82 1437.04,-1965.82 1446.35,-1956.5 v1(1449.06,-1956.5)
  Bottom Layer w10: C60.1@1426.24,-1961.95 1426.24,-1960.91 1428.74,-1958.41 1447.15,-1958.41 v1(1449.06,-1956.5)
NetC61_1: C61.1 R103.2 U10.8 | length 49.4
  Top Layer w10: U10.8@1368.34,-2011.09 1368.34,-2017.63 1393.35,-2042.63 1393.35,-2047.5 v1(1395.2,-2049.35)
NetC62_1: C62.1 R103.1 | length 38.9
  Bottom Layer w10: C62.1@1344.38,-2121.44 R103.1@1383.31,-2121.44
NetD1_2: D1.2 R61.1 | length 96.1
  Top Layer w10: v1(1522.73,-3446.21) 1564.52,-3446.21 D1.2@1566.18,-3444.55
  Bottom Layer w10: v1(1522.73,-3446.21) 1550.61,-3446.21 R61.1@1567.65,-3463.24
NetD4_1: D4.1 D11.2 Q2.3 | length 315.1
  Top Layer w10: D4.1@355.77,-2785.55 387.26,-2785.55 404.9,-2803.19 Q2.3@404.9,-2810.57 404.9,-2926.15 437.87,-2959.13 468.29,-2959.13 D11.2@509.79,-3000.63
NetD5_1: D5.1 J5.1 R25.1 | length 240.3
  Top Layer w10: v1(322.53,-1875.41) 359.58,-1875.41 D5.1@361.12,-1876.96 365.06,-1876.96 375.81,-1866.21 375.81,-1862.28 381.12,-1856.96 J5.1@381.12,-1726.33
  Bottom Layer w10: v1(322.53,-1875.41) 323.03,-1874.91 361.45,-1874.91 R25.1@361.96,-1874.4
NetD5_2: D5.2 R27.1 | length 80.5
  Top Layer w10: v1(321.53,-1956.88) 359.94,-1956.88 D5.2@361.12,-1955.7
  Bottom Layer w10: v1(321.53,-1956.88) 321.85,-1956.56 361.37,-1956.56 R27.1@361.69,-1956.24
NetD6_1: D6.1 J6.1 R26.1 | length 206.2
  Top Layer w10: D6.1@358.9,-1537.5 359.69,-1536.71 v1(359.69,-1490.91) 359.69,-1407.77 J6.1@381.12,-1386.33
  Bottom Layer w10: R26.1@358.08,-1536.11 359.69,-1534.5 v1(359.69,-1490.91)
NetD6_2: D6.2 R28.1 | length 82.2
  Top Layer w10: v1(319.15,-1613.33) 355.99,-1613.33 D6.2@358.9,-1616.24
  Bottom Layer w10: v1(319.15,-1613.33) 320.91,-1615.1 357.19,-1615.1 R28.1@358.95,-1616.86
NetD7_2: D7.2 R43.2 | length 78.8
  Top Layer w10: D7.2@211.12,-1955.7 211.42,-1955.4 v1(248.63,-1955.4)
  Bottom Layer w10: R43.2@208.34,-1957.57 209.43,-1956.49 247.55,-1956.49 v1(248.63,-1955.4)
NetD8_2: D8.2 R44.2 | length 82.9
  Top Layer w10: D8.2@208.12,-1615.7 210.18,-1617.77 v1(249.2,-1617.77)
  Bottom Layer w10: R44.2@207.65,-1617.64 v1@248.65,-1617.64
NetD9_1: D9.1 Q3.3 | length 233.8
  Top Layer w10: D9.1@1775.47,-3523.29 1779.41,-3523.29 1800.72,-3544.6 v1(1800.72,-3544.95)
  Bottom Layer w10: Q3.3@1723.95,-3403.16 1767.93,-3403.16 1790.86,-3426.09 1790.86,-3534.25 1800.72,-3544.12 v1(1800.72,-3544.95)
NetD9_2: D9.2 R33.1 | length 206
  Top Layer w10: v1(1724.02,-3440.78) 1771.71,-3440.78 D9.2@1775.47,-3444.55
  Bottom Layer w10: v1(1724.02,-3440.78) 1704.48,-3440.78 1698.62,-3434.93 1698.62,-3383.84 1746.4,-3336.05 R33.1@1752.9,-3336.05
NetD10_1: D10.1 Q1.3 | length 152.6
  Top Layer w10: D10.1@1883.02,-3523.86 1883.02,-3495.38 1912.71,-3465.7 1912.71,-3462.02 1924.73,-3449.99 v1(1924.73,-3447.37)
  Bottom Layer w10: Q1.3@1891.2,-3402.41 1891.2,-3410.29 1922.88,-3441.96 1922.88,-3445.52 v1(1924.73,-3447.37)
NetD10_2: D10.2 R1.1 | length 166.2
  Top Layer w10: v1(1836.21,-3443.01) 1880.91,-3443.01 D10.2@1883.02,-3445.12
  Bottom Layer w10: v1(1836.21,-3443.01) 1836.21,-3356.63 1856.21,-3336.63 R1.1@1860.09,-3336.63
NetD11_1: D11.1 J15.1 | length 412.3
  Top Layer w10: J15.1@156,-2940.11 207.28,-2991.39 207.28,-3049.17 231.39,-3073.28 384.11,-3073.28 399.55,-3057.85 D11.1@399.55,-3000.63 D11.1@388.16,-3012.02
NetD12_2: D12.2 L9.2 U10.13 U10.14
NetD13_2: D13.2 R109.1 | length 78.5
  Top Layer w10: R109.1@1291.4,-2288.94 1344.54,-2288.94 1359.69,-2304.09 D13.2@1359.69,-2308.03
NetD15_2: D15.2 R66.1 | length 172.5
  Top Layer w10: v1(1617.26,-3440.16) 1619.96,-3440.16 1624.35,-3444.55 D15.2@1670.83,-3444.55
  Bottom Layer w10: v1(1617.26,-3440.16) 1648.55,-3408.88 R66.1@1648.55,-3336.05
NetFB1_1: FB1.1 L7.2 | length 90.7
  Bottom Layer w30: FB1.1@1174.93,-2600.53 1179.13,-2604.74 L7.2@1179.13,-2689.46
NetJ5_3: J5.3 R43.1 | length 239.5
  Bottom Layer w10: R43.1@161.1,-1957.57 161.1,-1818.95 181.12,-1798.93 J5.3@181.12,-1726.33
NetJ6_3: J6.3 R44.1 | length 239.9
  Bottom Layer w10: R44.1@160.4,-1617.64 160.4,-1533.02 161.24,-1532.18 161.24,-1473.22 181.12,-1453.35 J6.3@181.12,-1386.33
NetJ11_1: J11.1 R21.1 | length 66
  Bottom Layer w10: R21.1@113.52,-584.66 178.92,-584.66 J11.1@179.34,-585.09
NetJ11_3: J11.3 R41.1 | length 172.2
  Top Layer w10: R41.1@360.21,-733.96 356.27,-733.96 349.46,-727.15 349.46,-723.21 344.37,-718.12 344.37,-620.07 J11.3@379.34,-585.09
NetJ16_1: J16.1 R2.2 | length 145.3
  Bottom Layer w10: J16.1@170.82,-831.09 170.82,-761 184.31,-747.51 R2.2@240.39,-747.51
NetL3_2: L3.2 R71.1 R73.1 | length 443.8
  Bottom Layer w30: L3.2@731.41,-1094.76 742.59,-1105.94 862.4,-1105.94 ; R73.1@911.06,-1070.71 911.06,-1071.69 876.81,-1105.94 862.4,-1105.94 ; R71.1@1094.2,-1120.21 1086.19,-1128.22 928.72,-1128.22 884.67,-1128.22 862.4,-1105.94
NetQ1_1: Q1.1 R68.2 | length 53.7
  Bottom Layer w10: Q1.1@1928.6,-3496.9 1928.93,-3497.23 1928.93,-3549.97 R68.2@1929.26,-3550.3
NetQ2_1: Q2.1 U6.1 U6.4 | length 186.6
  Top Layer w10: U6.4@240.87,-3010.95 240.87,-3001.1 308.86,-2933.11 308.86,-2915.4 U6.1@315.67,-2908.58 319.2,-2905.06 Q2.1@367.49,-2905.06
NetQ2_2: Q2.2 R77.1 | length 61.7
  Top Layer w10: Q2.2@442.3,-2905.06 497.84,-2905.06 R77.1@502.17,-2900.74
NetQ3_1: Q3.1 R93.2 | length 54.4
  Bottom Layer w10: Q3.1@1761.35,-3497.65 1761.35,-3550.6 R93.2@1762.35,-3551.6
NetQ5_3: Q5.3 R81.1 | length 97
  Top Layer w10: R81.1@287.19,-2644.83 366.1,-2644.83 372.96,-2651.7 Q5.3@381.33,-2651.7
NetR34_2: R34.2 R38.1 | length 413.9
  Top Layer w6: R38.1@2017.2,-786.9 2069.8,-839.49 2069.8,-1095.84 2035.18,-1130.47 2035.18,-1164.08 R34.2@2035.61,-1164.5
NetR76_1: R76.1 R79.1 R81.2 | length 109
  Top Layer w20: R79.1@224,-2753.78 224.19,-2753.59 R81.2@224.19,-2644.83
NetR78_1: R78.1 R80.2 U5.3 | length 129.5
  Bottom Layer w10: R80.2@358.83,-2665.26 359.06,-2665.49 R78.1@359.06,-2748.05 363.15,-2743.95 U5.3@403.97,-2743.95
NetR87_2: R87.2 U8.9 | length 96.4
  Top Layer w10: U8.9@548.3,-2454.33 548.77,-2453.85 643.84,-2453.85 R87.2@644.31,-2453.38
NetR90_2: R90.2 U9.13 | length 71.9
  Bottom Layer w10: U9.13@189.15,-2342.19 189.28,-2342.31 189.28,-2413.88 R90.2@189.4,-2414.01
NetR91_1: R91.1 R92.2 U9.2 | length 93.4
  Bottom Layer w10: R92.2@136.82,-2020.93 R91.1@136.82,-2059.93 137.4,-2060.51 137.4,-2113.27 U9.2@137.97,-2113.84
NetR95_1: R95.1 R96.1 | length 386.6
  Bottom Layer w10: R96.1@1337.4,-2170.01 1437.83,-2170.01 1539.65,-2068.19 R95.1@1539.65,-1926.06
NetR102_2: R102.2 U10.5 | length 83.6
  Top Layer w10: U10.5@1309.28,-2011.09 1309.56,-2011.37 1309.56,-2030.01 1317,-2037.46 v1(1317,-2040.08)
  Bottom Layer w10: R102.2@1299.83,-2081.7 1304.33,-2081.7 1317,-2069.03 v1(1317,-2040.08)
NetR104_2: R104.2 R106.1 U12.2 | length 90
  Bottom Layer w10: U12.2@1212.4,-2177.24 1212.4,-2133.32 1214.9,-2130.82 R104.2@1218.53,-2130.82 R106.1@1257.4,-2130.82
NetR105_2: R105.2 R107.1 U12.1 | length 94.1
  Bottom Layer w10: R107.1@1139.58,-2130.82 R105.2@1178.88,-2130.82 1183.38,-2130.82 1185.88,-2133.32 1185.88,-2137.82 1191.81,-2143.75 1191.81,-2176.33 U12.1@1192.71,-2177.24
NetR110_1: R110.1 R111.2 U11.5 | length 85.5
  Bottom Layer w10: U11.5@1963.52,-2780.06 1993.33,-2780.06 R110.1@1999.13,-2774.26 2002.02,-2777.15 R111.2@2045.4,-2777.15
NetR112_2: R112.2 U13.2 | length 71.4
  Top Layer w10: U13.2@1561.58,-2619.58 1561.67,-2619.49 v1(1614.01,-2619.4) v1(1614.01,-2619.4)
  Bottom Layer w10: R112.2@1612.91,-2637.88 1613.46,-2637.33 1613.46,-2619.95 v1(1614.01,-2619.4)
NetR113_2: R113.2 U13.3 | length 89.4
  Top Layer w10: U13.3@1561.58,-2593.99 1562.49,-2593.08 1600.4,-2593.08 1606.78,-2586.7 v1(1609.49,-2586.7)
  Bottom Layer w10: R113.2@1573.62,-2580.51 1600.59,-2580.51 1606.78,-2586.7 v1(1609.49,-2586.7)
NetR114_2: R114.2 U13.5 | length 85.4
  Top Layer w10: U13.5@1561.58,-2542.81 1561.98,-2543.21 1609.09,-2543.21 v1(1609.49,-2543.61)
  Bottom Layer w10: R114.2@1573.12,-2541.58 1574.14,-2542.59 1608.48,-2542.59 v1(1609.49,-2543.61)
NetR115_2: R115.2 U13.7 | length 82.4
  Top Layer w10: U13.7@1561.58,-2491.63 1562.07,-2491.14 1607.85,-2491.14 v1(1608.34,-2490.64)
  Bottom Layer w10: R115.2@1573.12,-2490.62 v1(1608.34,-2490.64)
NetR116_2: R116.2 U10.11 | length 86.4
  Top Layer w10: U10.11@1393.93,-1946.13 1424.12,-1946.13 v1(1448.27,-1921.98)
  Bottom Layer w10: R116.2@1426.24,-1922.14 1426.32,-1922.06 1448.19,-1922.06 v1(1448.27,-1921.98)
PG_1V: U3.6
PoDL_D+: J15.2 L2.2 L5.3 L6.2 L12.3 R82.2 R83.2 R109.2 U12.8 U13.8 U13.9 U13.10 | length 2575.7
  Top Layer w10: J15.2@156,-3040.11 211.28,-3095.4 512.95,-3095.4 587.14,-3021.2 587.14,-2826.34 516.84,-2756.03 516.84,-2566.36 557.2,-2526 698.89,-2526 754.64,-2470.25 ; R82.2@165.41,-2171.98 192.83,-2171.98 ; R83.2@220.26,-2171.98 192.83,-2171.98 ; v1(848.56,-2525.18) 809.57,-2525.18 754.64,-2470.25 ; R109.2@1244.16,-2288.94 1243.37,-2289.73 1243.37,-2379.61 1231.88,-2391.09 v1(1231.88,-2393.71) 1292.62,-2454.45 v1(1292.62,-2475.91) ; 192.83,-2171.98 192.83,-2140.67 248.62,-2084.89 340.49,-2084.89 368.69,-2113.08 368.69,-2225.31 392.49,-2249.11 628.56,-2249.11 754.64,-2375.19 754.64,-2470.25
  Bottom Layer w10: v1(1231.88,-2393.71) 1231.98,-2393.62 1231.98,-2350.57 U12.8@1232.08,-2350.47
  other v1: 871.21,-2571.64 848.25,-2555.02 893.58,-2554.41 871.53,-2541.8 1291.72,-2536.45 893.89,-2524.58 1292.31,-2505.74
PoDL_D-: FB1.2 L2.3 L5.4 L12.2 R108.2 TP9.1 U12.10 | length 172.2
  Top Layer w10: TP9.1@1104.34,-2553.79 1104.9,-2553.79 1134.06,-2524.63 v1(1134.62,-2524.63)
  Bottom Layer w10: R108.2@1186.05,-2477.58 1192.71,-2470.92 U12.10@1192.71,-2350.47
PSE_boost_out: C56.1 C69.1 C70.1 D12.1 J18.1 R95.2 TP10.1 | length 108.9
  Bottom Layer w10: R95.2@1539.65,-1866.06 1547.15,-1866.06 1566.1,-1847.11 1566.1,-1801.6 C70.1@1586.7,-1781.01
  other v1: 1675.3,-1797.89 1643.6,-1793.17 1676.35,-1769.07 1643.08,-1763.31
PSE_BOOST_VIN: C57.1 C58.1 J21.2 L9.1 U10.3 U10.6 | length 265.7
  Top Layer w10: U10.3@1283.69,-1965.82 1283.42,-1966.09 1261.5,-1966.09 1255.11,-1972.48 1254.5,-1972.48 1232.59,-1994.4 C58.1@1231.6,-1994.4 1233.6,-1996.4 v1(1233.6,-2026.96) 1271.94,-2065.31 1322.84,-2065.31 1336.85,-2051.29 1336.85,-2031.86 1333.93,-2028.94 1333.93,-2022.59 1328.97,-2017.63 U10.6@1328.97,-2011.09
  other v1: 1192.15,-1850.71 1192.15,-1822.67 1192.15,-1794.64 1192.15,-1766.6 1192.15,-1738.56 1192.15,-1710.53 1192.15,-1682.49
Q: J22.3 R42.1 R85.1 U8.6 U8.10 U9.5 | length 3286.4
  Top Layer w10: U8.6@316.01,-2454.33 316.41,-2454.73 366.05,-2454.73 v1(366.45,-2455.13) ; v1(495.53,-2429.42) 495.87,-2429.08 547.96,-2429.08 U8.10@548.3,-2428.74 594.8,-2428.74 613.27,-2410.27 R85.1@617.21,-2410.27
  Bottom Layer w6: v1(366.45,-2455.13) 392.16,-2429.42 v1(495.53,-2429.42) 495.53,-2253.22 396.81,-2154.51 224.26,-2154.51 218.4,-2148.65 218.4,-2117.5 U9.5@214.74,-2113.84 214.74,-2058.34 250.04,-2023.04 351.25,-2023.04 546.87,-2218.66 1049.86,-2218.66 1099.73,-2268.53 1339.15,-2268.53 1387.22,-2316.6 1387.22,-2421.56 1373.78,-2435 1373.78,-2778.96 1567.4,-2972.58 1608.06,-2972.58 J22.3@1614.54,-2979.06 1730.06,-2979.06 1772.43,-2936.68 R42.1@1772.43,-2834.56
Q_N: J17.3 R84.1 U8.4 U8.8 | length 957.3
  Top Layer w10: U8.4@316.01,-2403.15 401.59,-2403.15 478.2,-2479.76 v1(497.13,-2479.76) ; v1@497.13,-2479.27 497.7,-2479.84 548.22,-2479.84 U8.8@548.3,-2479.92 597.48,-2479.92 612.7,-2495.14 R84.1@616.63,-2495.14 ; J17.3@826.13,-2116.18 826.5,-2116.55 826.5,-2275.8 v1(826.87,-2276.17)
  Bottom Layer w6: v1(497.13,-2479.76) 540.92,-2435.97 540.92,-2362.3 606.37,-2296.86 719.01,-2296.86 740.71,-2275.16 825.85,-2275.16 v1(826.87,-2276.17)
RGMII_RX0: J2.68 R55.1 | length 50
  Top Layer w13.51: J2.68@789.01,-77 790.93,-78.92 790.93,-124.01 791.68,-124.75 R55.1@792.85,-124.75
RGMII_RX1: J2.70 R56.1 | length 50.3
  Top Layer w13.51: R56.1@753.36,-124.75 754.7,-124.75 755.44,-124.01 755.44,-79.08 J2.70@757.52,-77
RGMII_RX2: J2.72 R57.1 | length 896.2
  Top Layer w13.51: J2.72@726.02,-77 726.02,-526.82 816.5,-617.29 946.19,-617.29 1025.6,-696.7 v1(1025.6,-735.55)
  Bottom Layer w13.51: R57.1@1019.02,-769.77 1020.08,-769.77 1020.82,-769.02 1020.82,-742 1025.6,-737.22 v1(1025.6,-735.55)
RGMII_RX3: J2.74 R58.1 | length 894.1
  Top Layer w13.51: J2.74@694.53,-77 694.53,-548.87 786.69,-641.03 925.36,-641.03 v1(982.25,-697.92)
  Bottom Layer w13.51: R58.1@980.32,-769.77 980.54,-769.77 981.28,-769.02 981.28,-698.89 v1(982.25,-697.92)
RGMII_RX_CLK: J2.64 R54.1 | length 48
  Top Layer w13.51: R54.1@851.42,-124.75 851.71,-124.46 851.71,-77.29 J2.64@852.01,-77
RGMII_RX_CTRL: J2.60 R53.1 | length 50.4
  Top Layer w13.51: R53.1@910.69,-124.75 912.1,-124.75 912.84,-124.01 912.84,-79.15 J2.60@915,-77
RGMII_TX0: J2.48 R50.1 | length 797.5
  Top Layer w13.51: v1(1011.47,-498.83) 1011.47,-497.07 1026.81,-481.73 v1(1026.81,-375.14) ; J2.48@1103.97,-77 1104.15,-77.17 1104.15,-270.99 v1(1105.14,-271.98)
  Bottom Layer w13.51: R50.1@856.36,-771 856.36,-653.93 v1(1011.47,-498.83) ; v1(1026.81,-375.14) 1103.96,-297.99 1103.96,-273.16 v1(1105.14,-271.98)
RGMII_TX1: J2.46 R49.1 | length 793.7
  Top Layer w13.51: v1(1035.79,-522.4) 1071.2,-486.99 1071.2,-380.19 v1@1072.07,-379.32 ; J2.46@1135.47,-77 1135.74,-77.27 1135.74,-292.39 v1(1136.01,-292.66)
  Bottom Layer w13.51: R49.1@896.44,-771.74 896.44,-661.74 v1(1035.79,-522.4) ; v1(1071.2,-378.45) 1134.83,-314.82 1134.83,-293.84 v1(1136.01,-292.66)
RGMII_TX2: J2.44 R48.1 | length 50.1
  Top Layer w13.51: R48.1@1163.04,-124.75 1164.26,-124.75 1165,-124.01 1165,-78.96 J2.44@1166.97,-77
RGMII_TX3: J2.42 R47.1 | length 49.6
  Top Layer w13.51: J2.42@1198.46,-77 1200.06,-78.6 1200.06,-124.01 1200.81,-124.75 R47.1@1201.66,-124.75
RGMII_TX_CLK: J2.54 R51.1 | length 47.8
  Top Layer w13.51: R51.1@1009.46,-124.75 J2.54@1009.49,-77
RGMII_TX_CTRL: J2.58 R52.1 | length 49.8
  Top Layer w13.51: J2.58@946.49,-77 948.27,-78.77 948.27,-124.01 949.01,-124.75 R52.1@950.04,-124.75
SCL: J2.30 J3.24 R97.1 U9.14 U12.5 | length 4446.5
  Top Layer w6: v1(403.62,-2216.95) 404.65,-2216.95 502.33,-2119.27 v1(503.36,-2119.27) ; v1(1706.86,-796.1) 1706.86,-798.72 1720.13,-811.99 1720.13,-1218.77 1710.57,-1228.33 v1(1710.57,-1255.45)
  Top Layer w10: v1(1302.02,-346.4) 1387.44,-260.98 J2.30@1387.44,-77
  Bottom Layer w6: U9.14@163.56,-2342.19 163.56,-2255.52 195.46,-2223.63 393.26,-2223.63 399.93,-2216.95 v1(403.62,-2216.95) ; v1(503.36,-2119.27) 565.47,-2181.38 1066.67,-2181.38 1128.11,-2242.82 1261.25,-2242.82 1271.45,-2232.63 1271.45,-2218.4 ; U12.5@1271.45,-2177.24 1271.45,-2218.4 ; v1(1302.02,-346.4) 1302.02,-346.67 1319.45,-364.1 J3.24@1319.45,-434.25 1319.45,-483.19 1355.6,-519.33 1486.96,-519.33 1557.32,-589.7 1557.32,-676.84 1638.8,-758.32 1692.83,-758.32 1707.51,-773 1707.51,-795.45 v1(1706.86,-796.1) 1705.01,-797.95 1705.01,-818.77 1702.51,-821.27 R97.1@1699.05,-821.27 ; v1(1710.57,-1255.45) 1710.57,-1423.05 1768.71,-1481.19 1768.71,-2226.81 1698.67,-2296.84 1428.98,-2296.84 1350.53,-2218.4 1271.45,-2218.4
SDA: J2.28 J3.25 R98.1 U9.15 U12.4 | length 4480.9
  Top Layer w6: v1(399.11,-2190.93) 399.41,-2190.93 500.48,-2089.86 v1(500.77,-2089.86) ; v1(1244.65,-2223.34) 1247.27,-2223.34 1261.6,-2237.66 v1(1299.91,-2237.66) ; v1(1732.8,-1235.67) 1737.02,-1231.46 v1(1737.02,-796.26)
  Top Layer w10: v1(1340.4,-341.99) 1418.94,-263.46 J2.28@1418.94,-77
  Bottom Layer w6: U9.15@137.97,-2342.19 137.97,-2251.19 179.5,-2209.66 380.38,-2209.66 v1(399.11,-2190.93) ; v1(500.77,-2089.86) 574.22,-2163.3 1076.36,-2163.3 1142.53,-2229.47 1234.81,-2229.47 1240.95,-2223.34 v1(1244.65,-2223.34) ; v1@1249.5,-2214.78 1249.5,-2179.5 U12.4@1251.77,-2177.24 ; v1(1299.91,-2237.66) 1300.65,-2236.92 1352.38,-2236.92 1425.56,-2310.1 1709.68,-2310.1 1782.77,-2237.01 1782.77,-1479.07 1738.88,-1435.18 1732.8,-1429.1 v1(1732.8,-1235.67) ; v1(1340.4,-341.99) 1350.94,-352.54 J3.25@1350.94,-434.25 1350.94,-477.35 1377.99,-504.39 1491.62,-504.39 1570.67,-583.45 1570.67,-669.53 1644.59,-743.45 1707.78,-743.45 1737.02,-772.69 v1(1737.02,-796.26) 1738.87,-798.11 1738.87,-818.77 1741.37,-821.27 R98.1@1744.29,-821.27
SGMII_1_RX_N: C33.2 R39.1 | length 815.9
  Top Layer w6.73: C33.2@583.4,-297.74 587.54,-301.87 593.18,-301.87 597.12,-305.82 597.12,-631.43 648.86,-683.16 878.13,-683.16 919.74,-724.78 966.66,-724.78 993.8,-751.92 993.8,-761.69 989.86,-765.63 984.45,-765.63 R39.1@980.32,-769.77
SGMII_1_RX_P: C34.2 R40.1 | length 815.9
  Top Layer w6.73: C34.2@622.58,-297.74 618.44,-301.87 612.8,-301.87 608.86,-305.82 608.86,-626.57 653.72,-671.43 882.99,-671.43 924.6,-713.05 971.52,-713.05 1005.53,-747.06 1005.53,-761.69 1009.48,-765.63 1014.88,-765.63 R40.1@1019.02,-769.77
SGMII_1_TX_N: C36.2 R46.1 | length 89.6
  Top Layer w6.73: C36.2@827.58,-742.32 831.72,-738.19 831.72,-732.74 835.66,-728.79 845.38,-728.79 870.14,-753.54 870.14,-763.66 866.19,-767.61 859.69,-767.61 R46.1@855.56,-771.74
SGMII_1_TX_P: C1.2 R45.1 | length 106.1
  Top Layer w6.73: C1.2@827.58,-703.53 827.58,-703.92 831.72,-708.06 841.24,-708.06 881.87,-748.68 881.87,-763.66 885.81,-767.61 892.31,-767.61 R45.1@896.44,-771.74
SGMII_2_RX_N: C33.1 J2.88 J3.37 | length 632.5
  Top Layer w6.73: J2.88@474.05,-77 474.05,-96.29 483.94,-106.17 483.94,-162.44 511.5,-190.01 568.74,-190.01 597.12,-218.39 597.12,-244.02 592.04,-249.1 592.04,-253.6 587.9,-257.74 C33.1@583.4,-257.74
  Bottom Layer w6.73: v3(486.71,-177.9) 530.21,-134.39 753.49,-134.39 774.13,-155.04 774.13,-173.44 778.08,-177.38 778.52,-177.38 784.02,-182.87 J3.37@784.02,-195.67
SGMII_2_RX_P: C34.1 J2.86 J3.36 | length 571
  Top Layer w6.73: J2.86@505.55,-77 505.55,-96.29 495.67,-106.17 495.67,-157.58 516.36,-178.27 573.6,-178.27 608.86,-213.53 608.86,-244.02 613.94,-249.1 613.94,-253.6 618.08,-257.74 C34.1@622.58,-257.74
  Bottom Layer w6.73: v3(520.66,-169.92) 544.46,-146.13 748.63,-146.13 762.4,-159.9 762.4,-173.44 758.46,-177.38 758.01,-177.38 752.52,-182.87 J3.36@752.52,-195.67
SGMII_2_TX_N: C36.1 J2.94 J3.34 | length 1249
  Top Layer w6.73: J2.94@379.57,-77 379.57,-96.29 389.45,-106.17 389.45,-206.78 438.49,-255.82 438.49,-563.18 604.1,-728.79 779.51,-728.79 783.45,-732.74 783.45,-738.19 C36.1@787.58,-742.32
  Bottom Layer w6.73: v3(429.63,-282.85) 434.89,-277.6 514.47,-277.6 ccw(c518.27,-237.01) 522.06,-277.6 634.33,-277.6 679.65,-232.28 679.65,-217.9 683.59,-213.96 684.04,-213.96 689.53,-208.46 J3.34@689.53,-195.67
SGMII_2_TX_P: C1.1 J2.92 J3.33 | length 1181.2
  Top Layer w6.73: J2.92@411.06,-77 411.06,-96.29 401.18,-106.17 401.18,-201.92 450.22,-250.96 450.22,-558.32 608.96,-717.06 779.51,-717.06 783.45,-713.12 783.45,-707.66 C1.1@787.58,-703.53
  Bottom Layer w6.73: v3(459.3,-258.9) 462.89,-258.9 464.44,-260.46 469.85,-265.87 515.07,-265.87 ccw(c518.27,-237.01) 521.47,-265.87 629.47,-265.87 667.91,-227.42 667.91,-217.9 663.97,-213.96 663.52,-213.96 658.03,-208.46 J3.33@658.03,-195.67
SNS: R110.2 U13.6 | length 585.5
  Top Layer w10: U13.6@1561.58,-2517.22 1562.27,-2516.53 1623.52,-2516.53 v1(1624.21,-2515.83)
  Bottom Layer w10: v1(1624.21,-2515.83) 1640.39,-2532.02 1640.39,-2659.32 1707.55,-2726.48 1984.55,-2726.48 1984.61,-2726.54
TERM: C30.2 R11.1 R12.1 R13.2
TRD_2_N: L8.1 R9.2 R10.2 U2.2 | length 307.2
  Top Layer w6.73: R9.2@1035.44,-1624.53 1035.03,-1624.53 1030.9,-1628.66 R10.2@1030.9,-1655.41 1035.03,-1659.54 1035.03,-1672.89 1042.48,-1680.34 1042.48,-1741.68 1053.2,-1752.4 U2.2@1053.2,-1811.99 1053.2,-1819.86 1020.96,-1852.11 1020.96,-1871.82 1024.9,-1875.76 1026.33,-1875.76 1045.6,-1895.03 L8.1@1045.6,-1896.02
TRD_2_P: L8.2 R7.1 R8.2 U2.1 | length 305.8
  Top Layer w6.73: L8.2@984.58,-1896.02 984.58,-1895.03 1003.85,-1875.76 1005.28,-1875.76 1009.23,-1871.82 1009.23,-1850.69 978.4,-1819.86 U2.1@978.4,-1811.99 978.4,-1753.36 990.06,-1741.7 990.06,-1680.43 997.24,-1673.25 997.24,-1657.88 R7.1@999.71,-1655.41 999.71,-1628.6 R8.2@995.64,-1624.53
TRD_3_N: C20.2 L8.4 | length 59.7
  Top Layer w6.73: C20.2@1039.72,-2067.45 1045.6,-2061.56 L8.4@1045.6,-2010.19
TRD_3_P: C10.2 L8.3 | length 60
  Top Layer w6.73: L8.3@984.58,-2010.19 984.58,-2060.73 C10.2@991.3,-2067.45
TRD_4_N: C20.1 D2.1 J1.2 L2.4 L5.1 L7.1 L12.4 R11.2 | length 1177.1
  Top Layer w6.73: v1(1033.49,-2338.42) 1033.28,-2338.63 1021.21,-2338.63 ; C20.1@1039.72,-2126.13 1039.72,-2131.43 1021.21,-2149.93 1021.21,-2161.14 1021.21,-2338.63 ; J1.2@1049.9,-2848.54 1041.23,-2848.54 1020.33,-2827.65 1020.33,-2822.07 1021.21,-2821.19 1021.21,-2338.63
  Bottom Layer w6.73: L12.4@895.09,-2347.16 903.83,-2338.42 v1(1033.49,-2338.42)
  Bottom Layer w30: R11.2@1057.86,-2940.53 1049.9,-2932.57 J1.2@1049.9,-2848.54 1049.9,-2789.59 D2.1@1057.54,-2781.96 1068.41,-2771.09 L5.1@1068.41,-2697.82 L7.1@1067.27,-2696.69 ; L5.1@1068.41,-2697.82 L7.1@1068.41,-2678.13
TRD_4_P: C10.1 D3.1 J1.1 L2.1 L5.2 L6.1 L12.1 R12.2 | length 1168.5
  Top Layer w6.73: J1.1@979.03,-2848.54 1008.6,-2818.98 1008.6,-2817.21 1009.48,-2816.34 1009.48,-2358.25 ; C10.1@991.3,-2126.13 991.3,-2131.43 1009.48,-2149.61 1009.48,-2156.28 1009.48,-2358.25 ; v1(996.83,-2358.06) 997.03,-2358.25 1009.48,-2358.25
  Bottom Layer w6.73: v1(996.83,-2358.06) 1096.79,-2358.06 L12.1@1107.69,-2347.16
  Bottom Layer w30: L5.2@950.3,-2697.82 L5.2@950.3,-2695.02 ; L2.1@950.3,-2680.2 L5.2@950.3,-2697.82 ; L2.1@953.1,-2680.2 953.1,-2695.02 L5.2@950.3,-2697.82 ; R12.2@970.68,-2940.53 970.68,-2856.9 J1.1@979.03,-2848.54 979.03,-2785.01 D3.1@976.4,-2782.38 975.42,-2782.38 960.08,-2767.04 960.08,-2707.6 L5.2@950.3,-2697.82
TRD_N: C21.1 R9.1 U1.13 | length 226.9
  Top Layer w6.73: U1.13@1025.89,-1367.03 1025.89,-1373.92 1021.92,-1377.9 1021.92,-1452.76 1021.63,-1453.04 1021.63,-1538.49 1028.06,-1544.91 1028.06,-1580.39 1032.19,-1584.53 R9.1@1035.44,-1584.53
TRD_P: C9.2 R8.1 U1.12 | length 227.3
  Top Layer w6.73: R8.1@995.64,-1584.53 999.34,-1584.53 1003.48,-1580.39 1003.48,-1544.91 1009.9,-1538.49 1009.9,-1448.18 1010.18,-1447.9 1010.18,-1377.9 1006.21,-1373.92 U1.12@1006.21,-1367.03
V_GND: C64.2 R99.2 R100.2 Y1.4 Y2.4 | length 119.2
  Top Layer w10: v1(708.58,-1249.92) 729.53,-1249.91 737.07,-1242.37 Y2.4@747.47,-1242.37
  Bottom Layer w10: R100.2@672.45,-1291.24 C64.2@672.45,-1250.29 672.64,-1250.11 708.4,-1250.11 v1(708.58,-1249.92)
VDD1P0_P9: C15.1 C16.1 C17.1 C18.2 R72.2 U1.9 | length 285.9
  Top Layer w6: v1(903.07,-1332.75) 904.08,-1331.74 U1.9@931.41,-1331.74
  Bottom Layer w10: R72.2@690.31,-1388.48 690.31,-1352.79 710.62,-1332.48 C15.1@747.99,-1332.48 748.12,-1332.35 788.77,-1332.35 C16.1@788.9,-1332.22 789.01,-1332.33 830.69,-1332.33 C17.1@830.8,-1332.45 830.85,-1332.5 871.89,-1332.5 C18.2@871.94,-1332.55 872.04,-1332.65 902.97,-1332.65 v1(903.07,-1332.75)
VDD1P0_P21: C35.1 C38.1 C39.1 C40.2 R74.2 U1.21 | length 294.5
  Top Layer w10: U1.21@1159.75,-1292.23 1225.43,-1292.23 1230.01,-1287.65 v1(1232.63,-1287.65)
  Bottom Layer w10: C38.1@1195.94,-1380.38 C38.1@1195.94,-1380.38 ; v1(1232.63,-1287.65) 1217.15,-1303.13 C40.2@1196.59,-1303.13 1196.32,-1303.39 1196.32,-1341.46 C39.1@1196.06,-1341.72 1196,-1341.78 C38.1@1195.94,-1380.38 ; R74.2@1256.1,-1438.55 1256.1,-1437.57 1231.02,-1412.48 1230.03,-1412.48 1222.96,-1405.41 C35.1@1222.96,-1380.14 1222.84,-1380.26 1196.06,-1380.26 C38.1@1195.94,-1380.38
